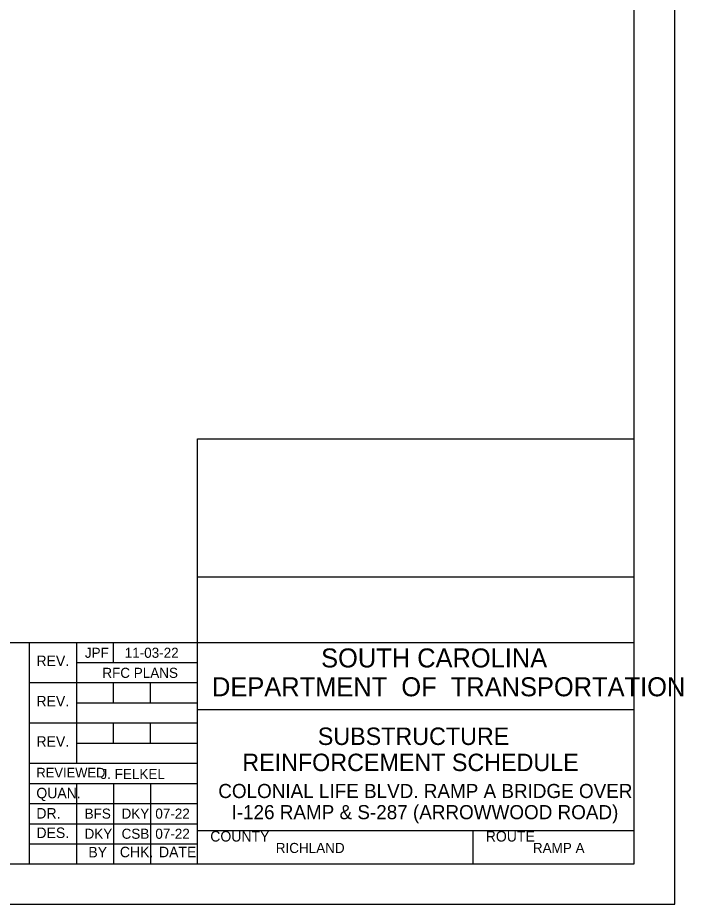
# Model space of a CAD drawing. Extents: x -121.2 to -24.9, y 6.4 to 65.
# Drawn here: x -46.89 to -24.88, y 6.35 to 35.68 of the extents above; entities that cross this region are included whole.
import ezdxf

# ---------------------------------------------------------------- set-up
doc = ezdxf.new("R2010")
doc.units = 0
for name, color, linetype in [('BR_BORDER LINES', 7, 'Continuous'), ('BR_TEXT', 7, 'Continuous'), ('Level 31', 7, 'Continuous')]:
    doc.layers.add(name, color=color, linetype=linetype)

msp = doc.modelspace()

# ---------------------------------------------------------------- linework, layer by layer
at = {"layer": 'BR_BORDER LINES'}
for p, q in [((-26.496, 7.683), (-26.496, 63.683)), ((-40.941, 7.683), (-40.941, 21.754)), ((-40.941, 21.754), (-26.496, 21.754)), ((-40.94, 17.182), (-26.496, 17.182)), ((-60.804, 15.017), (-46.496, 15.017)), ((-46.496, 7.683), (-46.496, 15.017)), ((-46.496, 15.017), (-26.496, 15.017)), ((-44.941, 15.017), (-44.941, 11.017)), ((-43.718, 14.35), (-43.718, 15.017)), ((-44.941, 14.35), (-40.941, 14.35)), ((-46.496, 13.684), (-40.941, 13.684)), ((-43.718, 13.017), (-43.718, 13.684)), ((-42.496, 13.017), (-42.496, 13.684)), ((-44.941, 13.017), (-40.941, 13.017)), ((-40.941, 12.795), (-40.941, 12.795)), ((-40.941, 12.795), (-26.495, 12.795)), ((-46.496, 12.35), (-40.941, 12.35)), ((-43.718, 11.684), (-43.718, 12.35)), ((-42.496, 11.684), (-42.496, 12.35)), ((-44.941, 11.684), (-40.941, 11.684)), ((-46.496, 11.017), (-40.941, 11.017)), ((-46.496, 10.35), (-40.941, 10.35)), ((-44.941, 10.35), (-44.941, 7.683)), ((-43.718, 10.35), (-43.718, 7.683)), ((-42.496, 10.35), (-42.496, 7.683)), ((-46.496, 9.683), (-40.941, 9.683)), ((-46.496, 9.017), (-40.941, 9.017)), ((-40.941, 8.795), (-26.496, 8.795)), ((-40.68, 8.795), (-26.496, 8.795)), ((-31.829, 7.683), (-31.829, 8.795)), ((-46.496, 8.35), (-40.941, 8.35)), ((-116.272, 7.683), (-26.496, 7.683))]:
    msp.add_line(p, q, dxfattribs=at)
at = {"layer": 'Level 31'}
msp.add_line((-33.717, 11.621), (-33.717, 11.621), dxfattribs=at)
msp.add_lwpolyline([(-121.161, 65.017), (-121.161, 6.35), (-25.161, 6.35), (-25.161, 65.017)], dxfattribs=at)

# ---------------------------------------------------------------- texts
at = {"layer": 'BR_TEXT'}
for s, height, p in [('JPF', 0.3333, (-44.669, 14.505)), ('11-03-22', 0.3333, (-43.351, 14.505)), ('SOUTH CAROLINA', 0.62899, (-36.855, 14.186)), ('REV.', 0.3467, (-46.27, 14.231)), ('RFC PLANS', 0.3333, (-44.091, 13.841)), ('DEPARTMENT  OF  TRANSPORTATION', 0.62899, (-40.463, 13.232)), ('REV.', 0.3467, (-46.27, 12.898)), ('SUBSTRUCTURE', 0.576, (-36.965, 11.621)), ('REV.', 0.3467, (-46.27, 11.565)), ('REINFORCEMENT SCHEDULE', 0.576, (-39.462, 10.757)), ('REVIEWED', 0.32, (-46.272, 10.546)), ('J. FELKEL', 0.3333, (-44.152, 10.495)), ('COLONIAL LIFE BLVD. RAMP A BRIDGE OVER', 0.46667, (-40.256, 9.865)), ('QUAN.', 0.3467, (-46.274, 9.857)), ('DR.', 0.3467, (-46.273, 9.186)), ('BFS', 0.3333, (-44.677, 9.183)), ('DKY', 0.3333, (-43.456, 9.183)), ('07-22', 0.3333, (-42.338, 9.183)), ('I-126 RAMP & S-287 (ARROWWOOD ROAD)', 0.46667, (-39.818, 9.165)), ('DES.', 0.3467, (-46.271, 8.543)), ('DKY', 0.3333, (-44.679, 8.517)), ('CSB', 0.3333, (-43.454, 8.517)), ('07-22', 0.3333, (-42.338, 8.517)), ('COUNTY', 0.3467, (-40.521, 8.425)), ('ROUTE', 0.3467, (-31.41, 8.425)), ('BY', 0.3467, (-44.553, 7.902)), ('CHK.', 0.3467, (-43.511, 7.906)), ('DATE', 0.3467, (-42.217, 7.906)), ('RICHLAND', 0.3333, (-38.355, 8.047)), ('RAMP A', 0.3333, (-29.851, 8.047))]:
    msp.add_text(s, height=height, dxfattribs=at).set_placement(p)

doc.saveas('drawing.dxf')
